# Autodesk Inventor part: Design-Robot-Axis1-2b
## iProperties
Created: 2008-03
Part Number: Design-Robot-Axis1-2b
Document SubType Name: Modeling
Designer: Admin
Density: 1 g/cm^3
Author: Admin
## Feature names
1. Extrusion1
2. Extrusion2
